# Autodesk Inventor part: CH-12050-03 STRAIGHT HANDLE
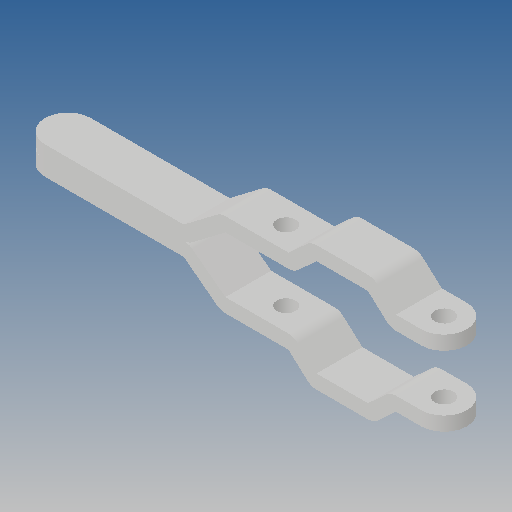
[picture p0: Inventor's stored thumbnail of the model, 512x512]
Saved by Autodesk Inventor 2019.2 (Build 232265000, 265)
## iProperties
Created: 2015-08
Part Number: CH-12050-03 STRAIGHT HANDLE
Material: Ogólny
Document SubType Name: Modeling
Designer: CADENGINEERING4
Density: 1 g/cm^3
Appearance: Domyślna
Author: CADENGINEERING4
Revision Number: ÈÎºÎ
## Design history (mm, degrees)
feature "ÇÐ³ý-À­Éì1"
feature "¾µÏò1"
node "Bryła1"
node "Bryła2"
